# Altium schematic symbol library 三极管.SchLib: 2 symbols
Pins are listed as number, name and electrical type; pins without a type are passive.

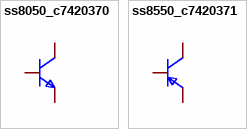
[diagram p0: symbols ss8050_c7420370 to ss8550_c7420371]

## ss8050_c7420370
designator Q??  (value not drawn)
晶体管类型:NPN;集电极电流(Ic):1.5A;集射极击穿电压(Vceo):25V;耗散功率(Pd):300mW;直流电流增益(hFE):120;; Manufacturer: R+O(宏嘉诚); ManufacturerPart: SS8050; AddInBom: yes; ModelId: c62791f0466c4ae2a892c056b845b0ca; ModelName: SOT-23-3P_L2.9-W1.3-H1.0-LS2.4-P0.95; ModelTransform: 98.425,114.173,0,180,0,0,0.0005,-0.0005,0; type: NPN; Current - Collector(Ic): 1.5A; Collector - Emitter Voltage VCEO: 25V; Pd - Power Dissipation: 300mW; DC Current Gain: 120; Transition frequency(fT): 100MHz; Current - Collector Cutoff: 100nA; Vce Saturation(VCE(sat)): 500mV; Emitter-Base Voltage(Vebo): 5V; Number: 1个NPN; Configuration: 独立式
footprint SOT-23-3_L2.9-W1.3-P1.90-LS2.4-BR
pins: 1 B, 2 E, 3 C

## ss8550_c7420371
designator Q??  (value not drawn)
晶体管类型:PNP;集电极电流(Ic):1.5A;集射极击穿电压(Vceo):25V;耗散功率(Pd):300mW;直流电流增益(hFE):120;; Manufacturer: R+O(宏嘉诚); ManufacturerPart: SS8550; AddInBom: yes; ModelId: c62791f0466c4ae2a892c056b845b0ca; ModelName: SOT-23-3P_L2.9-W1.3-H1.0-LS2.4-P0.95; ModelTransform: 98.425,114.173,0,180,0,0,0.0005,-0.0005,0; type: PNP; Current - Collector(Ic): 1.5A; Collector - Emitter Voltage VCEO: 25V; Pd - Power Dissipation: 300mW; DC Current Gain: 120; Transition frequency(fT): 100MHz; Current - Collector Cutoff: 100nA; Vce Saturation(VCE(sat)): 500mV; Emitter-Base Voltage(Vebo): 5V; Number: 1个PNP; Configuration: 独立式
footprint SOT-23-3_L2.9-W1.3-P1.90-LS2.4-BR
pins: 1 B, 2 E, 3 C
